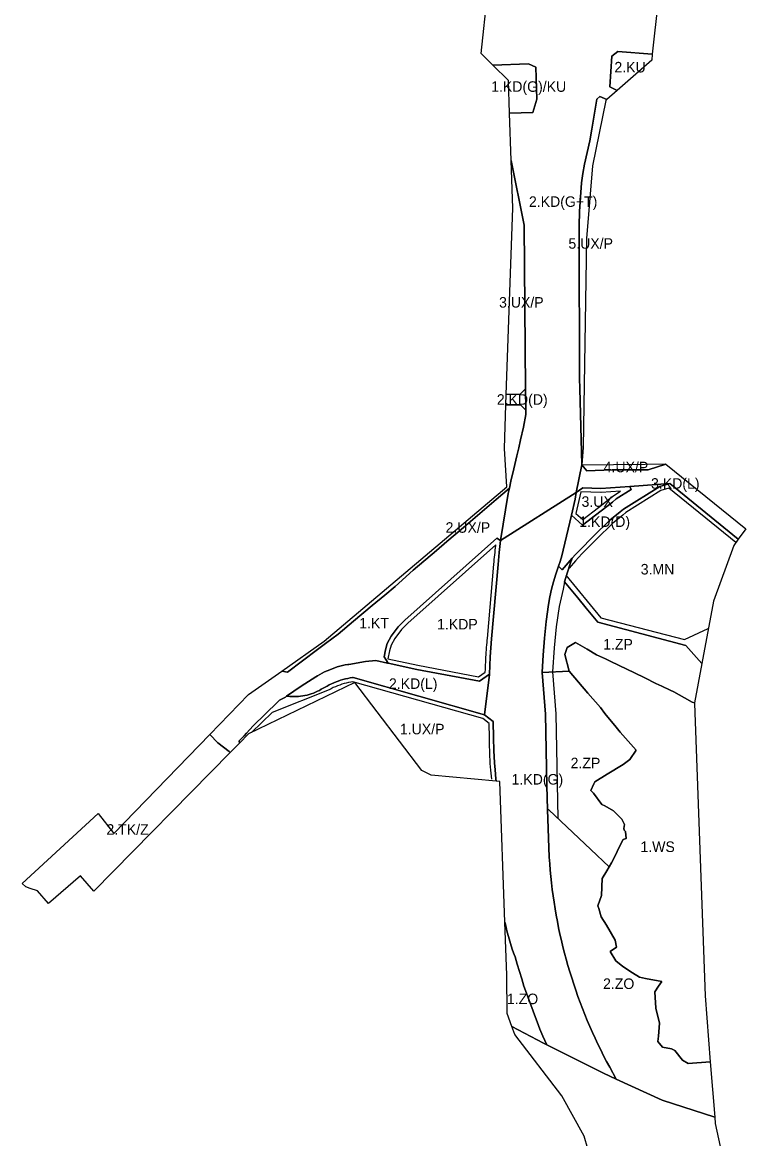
# Model space of a CAD drawing. Extents: x 7426363 to 7427567, y 5543397 to 5546605.
# Drawn here: x 7426639 to 7427327, y 5544381 to 5545441 of the extents above; entities that cross this region are included whole.
import ezdxf

# ---------------------------------------------------------------- set-up
doc = ezdxf.new("R2010")
doc.units = 0
for name, color, linetype in [('linie_rozgraniczajace', 7, 'Continuous'), ('linie_zabudowy_nieprzekraczalne', 7, 'Continuous'), ('oznaczenia_przeznaczen', 7, 'Continuous')]:
    doc.layers.add(name, color=color, linetype=linetype)

msp = doc.modelspace()

# ---------------------------------------------------------------- linework, layer by layer
at = {"layer": 'linie_rozgraniczajace'}
for points in [[(7427243.5, 5545461.5), (7427238, 5545410.3), (7427205.1, 5545413.1), (7427199.7, 5545408.5), (7427197.6, 5545379.3), (7427204.7, 5545376), (7427194.8, 5545367.3), (7427188.1, 5545370.2), (7427185.4, 5545367.6), (7427180.7, 5545339.4), (7427178.5, 5545328.2), (7427173.6, 5545306.2), (7427171.9, 5545297.3), (7427170.8, 5545288.4), (7427169.7, 5545274.8), (7427168.9, 5545261.2), (7427168.5, 5545247.6), (7427168.4, 5545234), (7427168.7, 5545106.2), (7427168.7, 5545102.7), (7427169.2, 5545093.1), (7427171, 5545020.6), (7427165.8, 5544994.3), (7427093.9, 5544949), (7427101.2, 5544993.4), (7427102.2, 5544998.5), (7427103.6, 5545005.2), (7427106.3, 5545016.9), (7427109.3, 5545029.3), (7427111.1, 5545036.8), (7427112.7, 5545044.4), (7427115.5, 5545056.4), (7427117.7, 5545068.5), (7427117.7, 5545072.7), (7427117.5, 5545092.7), (7427116.3, 5545248.3), (7427104, 5545309.5), (7427102.4, 5545354.4), (7427124.6, 5545355.2), (7427128.4, 5545367.6), (7427127.4, 5545398), (7427120.5, 5545401.3), (7427086.5, 5545400.1), (7427075.4, 5545411.1), (7427081.5, 5545467.8)], [(7427187.3, 5544335.4), (7427173.3, 5544383.6), (7427151.9, 5544421.9), (7427107.4, 5544479.9), (7427104.7, 5544487.5), (7427134.6, 5544471.8), (7427137.7, 5544470.2), (7427191.5, 5544443.3), (7427203.7, 5544437.7), (7427247.3, 5544417.6), (7427297.3, 5544401.6), (7427297.8, 5544395.4), (7427304, 5544366.5)]]:
    msp.add_lwpolyline(points, dxfattribs=at)
for points in [[(7427197.6, 5545379.3), (7427199.7, 5545408.5), (7427205.1, 5545413.1), (7427238, 5545410.3), (7427237.4, 5545404.8), (7427204.7, 5545376)], [(7427086.5, 5545400.1), (7427120.5, 5545401.3), (7427127.4, 5545398), (7427128.4, 5545367.6), (7427124.6, 5545355.2), (7427102.4, 5545354.4), (7427101.3, 5545385.4)], [(7427171, 5545020.6), (7427169.2, 5545093.1), (7427168.7, 5545102.7), (7427168.7, 5545106.2), (7427168.4, 5545234), (7427168.5, 5545247.6), (7427168.9, 5545261.2), (7427169.7, 5545274.8), (7427170.8, 5545288.4), (7427171.9, 5545297.3), (7427173.6, 5545306.2), (7427178.5, 5545328.2), (7427180.7, 5545339.4), (7427185.4, 5545367.6), (7427188.1, 5545370.2), (7427194.8, 5545367.3), (7427193.9, 5545366.5), (7427181.1, 5545304.6), (7427175.6, 5545235.4), (7427172.2, 5545037)], [(7427099.3, 5545087.5), (7427105.6, 5545264.4), (7427104, 5545309.5), (7427116.3, 5545248.3), (7427117.5, 5545092.7), (7427112.6, 5545087.7)], [(7427099, 5545077.5), (7427099.3, 5545087.5), (7427112.6, 5545087.7), (7427117.5, 5545092.7), (7427117.7, 5545072.7), (7427112.7, 5545077.7)], [(7426885.9, 5544824.8), (7426926.3, 5544853.3), (7427099.7, 5544999.9), (7427097.5, 5545036.2), (7427099, 5545077.5), (7427112.7, 5545077.7), (7427117.7, 5545072.7), (7427117.7, 5545068.5), (7427115.5, 5545056.4), (7427112.7, 5545044.4), (7427111.1, 5545036.8), (7427109.3, 5545029.3), (7427106.3, 5545016.9), (7427103.6, 5545005.2), (7427102.2, 5544998.5), (7427089.6, 5544987.7), (7427074, 5544974.4), (7427058.5, 5544961.1), (7427042.9, 5544947.9), (7427033, 5544939.5), (7427010.7, 5544920.7), (7426993.7, 5544905.1), (7426983.9, 5544897), (7426971.8, 5544887.1), (7426954.1, 5544872.4), (7426939.4, 5544860), (7426927.6, 5544851.1), (7426919.9, 5544845.4), (7426891.3, 5544823.9)], [(7427165.8, 5544994.3), (7427171, 5545020.6), (7427175.9, 5545015.1), (7427200, 5545015.8), (7427234.1, 5545015.8), (7427251, 5545021.2), (7427326.7, 5544960), (7427319.7, 5544950.2), (7427254.5, 5545002.9), (7427216.5, 5545000.2), (7427189.2, 5544998.3), (7427172, 5544999)], [(7427171, 5545020.6), (7427231.3, 5545021.3), (7427250.4, 5545021.7), (7427251, 5545021.2), (7427234.1, 5545015.8), (7427200, 5545015.8), (7427175.9, 5545015.1)], [(7427148.9, 5544924.6), (7427150.4, 5544929), (7427152, 5544934.2), (7427153.4, 5544939.6), (7427161.1, 5544973), (7427171.7, 5544963.5), (7427189.5, 5544977), (7427200.1, 5544985.4), (7427203.7, 5544988.3), (7427217.8, 5544997.2), (7427216.5, 5545000.2), (7427254.5, 5545002.9), (7427245, 5545000.2), (7427210.7, 5544978.5), (7427207.5, 5544976), (7427197.5, 5544968), (7427182.4, 5544953.3), (7427168.5, 5544939.2), (7427164.9, 5544935.5), (7427161.9, 5544932.2), (7427161.8, 5544932.1), (7427152.3, 5544921.1)], [(7427154.5, 5544909.7), (7427155.7, 5544913.6), (7427159.8, 5544925.8), (7427161.8, 5544932.1), (7427161.9, 5544932.2), (7427164.9, 5544935.5), (7427168.5, 5544939.2), (7427182.4, 5544953.3), (7427197.5, 5544968), (7427207.5, 5544976), (7427210.7, 5544978.5), (7427245, 5545000.2), (7427254.5, 5545002.9), (7427319.7, 5544950.2), (7427315.3, 5544944.1), (7427296.1, 5544891.4), (7427285, 5544832.2), (7427269.9, 5544849.3), (7427186.3, 5544871.2), (7427175.1, 5544884.7), (7427167.4, 5544894.4), (7427157.9, 5544905.7)], [(7426817.6, 5544764.8), (7426854.3, 5544802.7), (7426885.9, 5544824.8), (7426891.3, 5544823.9), (7426919.9, 5544845.4), (7426927.6, 5544851.1), (7426939.4, 5544860), (7426954.1, 5544872.4), (7426971.8, 5544887.1), (7426983.9, 5544897), (7426993.7, 5544905.1), (7427010.7, 5544920.7), (7427033, 5544939.5), (7427042.9, 5544947.9), (7427058.5, 5544961.1), (7427074, 5544974.4), (7427089.6, 5544987.7), (7427102.2, 5544998.5), (7427101.2, 5544993.4), (7427093.9, 5544949), (7427090.4, 5544951.2), (7427003, 5544873.4), (7426996.7, 5544867), (7426990, 5544858), (7426986.1, 5544851), (7426984.4, 5544845.2), (7426983.2, 5544838.4), (7426987.1, 5544832.4), (7426986.5, 5544832.5), (7426975.3, 5544834.9), (7426965.6, 5544834), (7426949.7, 5544831.3), (7426948.8, 5544831.2), (7426946.2, 5544830.7), (7426943.7, 5544830.1), (7426941.2, 5544829.5), (7426938.7, 5544828.8), (7426936.3, 5544828), (7426933.9, 5544827.2), (7426931.5, 5544826.2), (7426929.1, 5544825.2), (7426926.7, 5544824.1), (7426924.4, 5544823), (7426922.2, 5544821.7), (7426920, 5544820.5), (7426918.3, 5544819.6), (7426904.5, 5544810.5), (7426890.6, 5544801.1), (7426889.5, 5544800.3), (7426883.9, 5544797.3), (7426881.9, 5544795.3), (7426858.9, 5544773.1), (7426852.4, 5544765.9), (7426850.2, 5544763.5), (7426845.4, 5544758.7), (7426845.8, 5544756.5), (7426836.9, 5544747.6), (7426836, 5544748.6), (7426825.1, 5544756.9)], [(7427078.7, 5544783.4), (7427083.2, 5544821.6), (7427083.2, 5544821.9), (7427084, 5544838.6), (7427085.3, 5544855.5), (7427091.5, 5544926), (7427092.6, 5544937.5), (7427093.9, 5544949), (7427165.8, 5544994.3), (7427164.6, 5544988.2), (7427161.1, 5544973), (7427153.4, 5544939.6), (7427152, 5544934.2), (7427150.4, 5544929), (7427148.9, 5544924.6), (7427146.2, 5544916.8), (7427144.1, 5544909.7), (7427142.2, 5544902.6), (7427140.7, 5544895.3), (7427139.5, 5544888.1), (7427137.3, 5544872.1), (7427135.5, 5544856.1), (7427134.2, 5544840), (7427133.3, 5544824), (7427133.3, 5544823.6), (7427136.5, 5544783.9), (7427137.7, 5544716.1), (7427138.5, 5544693.6), (7427140.1, 5544648.3), (7427140.5, 5544642.1), (7427141, 5544636), (7427141.6, 5544629.9), (7427142.2, 5544623.8), (7427143, 5544617.7), (7427143.8, 5544611.5), (7427144.7, 5544605.5), (7427145.6, 5544599.4), (7427146.7, 5544593.3), (7427147.8, 5544587.3), (7427149, 5544581.3), (7427150.3, 5544575.2), (7427151.7, 5544569.3), (7427153.1, 5544563.3), (7427154.6, 5544557.3), (7427156.2, 5544551.4), (7427157.8, 5544545.5), (7427159.6, 5544539.6), (7427161.4, 5544533.7), (7427163.3, 5544527.8), (7427165.2, 5544522), (7427167.3, 5544516.2), (7427169.4, 5544510.4), (7427171.6, 5544504.7), (7427173.9, 5544499), (7427176.2, 5544493.3), (7427178.6, 5544487.6), (7427181.1, 5544482), (7427183.6, 5544476.4), (7427186.3, 5544470.9), (7427189, 5544465.3), (7427191.7, 5544459.8), (7427194.6, 5544454.4), (7427197.5, 5544449), (7427203.7, 5544437.7), (7427191.5, 5544443.3), (7427137.7, 5544470.2), (7427134.1, 5544478.5), (7427131.3, 5544485.2), (7427128.6, 5544492), (7427126, 5544498.7), (7427123.4, 5544505.5), (7427120.9, 5544512.3), (7427118.5, 5544519.2), (7427116.1, 5544526), (7427113.9, 5544532.9), (7427111.7, 5544539.8), (7427109.5, 5544546.8), (7427107.6, 5544553.6), (7427106.7, 5544555.8), (7427105.3, 5544560), (7427103.9, 5544564.3), (7427102.6, 5544568.6), (7427101.4, 5544572.9), (7427100.2, 5544577.2), (7427099.1, 5544581.5), (7427098.2, 5544585.9), (7427098, 5544586.7), (7427093.2, 5544720), (7427089.7, 5544720.3), (7427089.5, 5544722.5), (7427088.7, 5544731.3), (7427088.1, 5544737.7), (7427087.5, 5544749.6), (7427087.2, 5544761.6), (7427086.9, 5544777)], [(7427161.1, 5544973), (7427164.6, 5544988.2), (7427165.8, 5544994.3), (7427172, 5544999), (7427189.2, 5544998.3), (7427216.5, 5545000.2), (7427217.8, 5544997.2), (7427203.7, 5544988.3), (7427200.1, 5544985.4), (7427189.5, 5544977), (7427171.7, 5544963.5)], [(7426983.2, 5544838.4), (7426984.4, 5544845.2), (7426986.1, 5544851), (7426990, 5544858), (7426996.7, 5544867), (7427003, 5544873.4), (7427090.4, 5544951.2), (7427093.9, 5544949), (7427092.6, 5544937.5), (7427091.5, 5544926), (7427085.3, 5544855.5), (7427084, 5544838.6), (7427083.2, 5544821.9), (7427073.9, 5544815.4), (7427014.4, 5544826.5), (7426987.1, 5544832.4)], [(7427133.3, 5544824), (7427134.2, 5544840), (7427135.5, 5544856.1), (7427137.3, 5544872.1), (7427139.5, 5544888.1), (7427140.7, 5544895.3), (7427142.2, 5544902.6), (7427144.1, 5544909.7), (7427146.2, 5544916.8), (7427148.9, 5544924.6), (7427152.3, 5544921.1), (7427161.8, 5544932.1), (7427159.8, 5544925.8), (7427155.7, 5544913.6), (7427154.5, 5544909.7), (7427157.9, 5544905.7), (7427167.4, 5544894.4), (7427175.1, 5544884.7), (7427186.3, 5544871.2), (7427269.9, 5544849.3), (7427285, 5544832.2), (7427278.1, 5544794.7), (7427275.8, 5544795.5), (7427268.5, 5544799.6), (7427258.6, 5544805.3), (7427255, 5544806.9), (7427247.1, 5544810.7), (7427241.5, 5544813.2), (7427230.8, 5544818.4), (7427221, 5544823.3), (7427206.6, 5544830.2), (7427197.9, 5544834.3), (7427193.4, 5544836.4), (7427185, 5544840.4), (7427176, 5544845.8), (7427164.9, 5544852.2), (7427157.2, 5544847.4), (7427155, 5544840.8), (7427159.1, 5544824.7), (7427133.3, 5544823.6)], [(7427155, 5544840.8), (7427157.2, 5544847.4), (7427164.9, 5544852.2), (7427176, 5544845.8), (7427185, 5544840.4), (7427193.4, 5544836.4), (7427197.9, 5544834.3), (7427206.6, 5544830.2), (7427221, 5544823.3), (7427230.8, 5544818.4), (7427241.5, 5544813.2), (7427247.1, 5544810.7), (7427255, 5544806.9), (7427258.6, 5544805.3), (7427268.5, 5544799.6), (7427275.8, 5544795.5), (7427278.1, 5544794.7), (7427278, 5544794.3), (7427288.1, 5544516.8), (7427293, 5544454.2), (7427272, 5544452.5), (7427266.7, 5544455.5), (7427259.4, 5544464.8), (7427256.3, 5544466.5), (7427247.7, 5544468.1), (7427243.2, 5544473.4), (7427243.8, 5544478.4), (7427244.8, 5544490.6), (7427241.4, 5544505), (7427240.3, 5544520.6), (7427243.8, 5544526), (7427246.9, 5544530.3), (7427231.5, 5544533.3), (7427225.7, 5544534.3), (7427219.1, 5544538.6), (7427209.9, 5544544.4), (7427203.5, 5544549.9), (7427198, 5544558.7), (7427204, 5544562.9), (7427202.8, 5544569.4), (7427194.4, 5544583.8), (7427189.5, 5544591.6), (7427187.3, 5544599.6), (7427186.4, 5544602.1), (7427189.6, 5544611.9), (7427190.3, 5544628), (7427194.7, 5544635.3), (7427197, 5544639.2), (7427199.2, 5544642.8), (7427201.7, 5544647.7), (7427207.6, 5544659.7), (7427210.4, 5544665.1), (7427213.1, 5544665.9), (7427212.4, 5544672.6), (7427211.2, 5544673.9), (7427211.1, 5544675.4), (7427211.5, 5544679.2), (7427208.9, 5544684.3), (7427201.2, 5544692.3), (7427193, 5544696.9), (7427190.2, 5544698.4), (7427182, 5544708.9), (7427179.7, 5544711.6), (7427182.4, 5544718), (7427183.5, 5544719.9), (7427195, 5544727), (7427210.2, 5544736.4), (7427216.5, 5544741), (7427222.7, 5544749.8), (7427207.4, 5544766.8), (7427203.6, 5544771.7), (7427193, 5544784.8), (7427188.9, 5544790.2), (7427176.9, 5544804.1), (7427159.1, 5544824.7)], [(7426890.6, 5544801.1), (7426904.5, 5544810.5), (7426918.3, 5544819.6), (7426920, 5544820.5), (7426922.2, 5544821.7), (7426924.4, 5544823), (7426926.7, 5544824.1), (7426929.1, 5544825.2), (7426931.5, 5544826.2), (7426933.9, 5544827.2), (7426936.3, 5544828), (7426938.7, 5544828.8), (7426941.2, 5544829.5), (7426943.7, 5544830.1), (7426946.2, 5544830.7), (7426948.8, 5544831.2), (7426949.7, 5544831.3), (7426965.6, 5544834), (7426975.3, 5544834.9), (7426986.5, 5544832.5), (7426987.1, 5544832.4), (7427014.4, 5544826.5), (7427073.9, 5544815.4), (7427083.2, 5544821.9), (7427083.2, 5544821.6), (7427078.7, 5544783.4), (7426953.7, 5544818.9), (7426953.3, 5544818.8), (7426951, 5544818.5), (7426948.7, 5544818), (7426946.4, 5544817.5), (7426944.1, 5544816.9), (7426941.9, 5544816.2), (7426939.7, 5544815.5), (7426937.5, 5544814.7), (7426935.3, 5544813.8), (7426933.2, 5544812.8), (7426931.1, 5544811.8), (7426929, 5544810.7), (7426923.5, 5544807.6), (7426921.7, 5544806.6), (7426919.8, 5544805.7), (7426917.9, 5544804.9), (7426916, 5544804.1), (7426914, 5544803.4), (7426912, 5544802.8), (7426910, 5544802.2), (7426908, 5544801.8), (7426906, 5544801.4), (7426903.9, 5544801.1), (7426901.8, 5544800.9), (7426899.8, 5544800.7), (7426897.7, 5544800.7), (7426895.6, 5544800.7), (7426893.5, 5544800.8), (7426891.5, 5544801)], [(7427138.5, 5544693.6), (7427137.7, 5544716.1), (7427136.5, 5544783.9), (7427133.3, 5544823.6), (7427159.1, 5544824.7), (7427176.9, 5544804.1), (7427188.9, 5544790.2), (7427193, 5544784.8), (7427203.6, 5544771.7), (7427207.4, 5544766.8), (7427222.7, 5544749.8), (7427216.5, 5544741), (7427210.2, 5544736.4), (7427195, 5544727), (7427183.5, 5544719.9), (7427182.4, 5544718), (7427179.7, 5544711.6), (7427182, 5544708.9), (7427190.2, 5544698.4), (7427193, 5544696.9), (7427201.2, 5544692.3), (7427208.9, 5544684.3), (7427211.5, 5544679.2), (7427211.1, 5544675.4), (7427211.2, 5544673.9), (7427212.4, 5544672.6), (7427213.1, 5544665.9), (7427210.4, 5544665.1), (7427207.6, 5544659.7), (7427201.7, 5544647.7), (7427199.2, 5544642.8), (7427197, 5544639.2), (7427179.5, 5544655.7), (7427139.6, 5544693.2)], [(7426845.4, 5544758.7), (7426850.2, 5544763.5), (7426852.4, 5544765.9), (7426858.9, 5544773.1), (7426881.9, 5544795.3), (7426883.9, 5544797.3), (7426889.5, 5544800.3), (7426890.6, 5544801.1), (7426891.5, 5544801), (7426893.5, 5544800.8), (7426895.6, 5544800.7), (7426897.7, 5544800.7), (7426899.8, 5544800.7), (7426901.8, 5544800.9), (7426903.9, 5544801.1), (7426906, 5544801.4), (7426908, 5544801.8), (7426910, 5544802.2), (7426912, 5544802.8), (7426914, 5544803.4), (7426916, 5544804.1), (7426917.9, 5544804.9), (7426919.8, 5544805.7), (7426921.7, 5544806.6), (7426923.5, 5544807.6), (7426929, 5544810.7), (7426931.1, 5544811.8), (7426933.2, 5544812.8), (7426935.3, 5544813.8), (7426937.5, 5544814.7), (7426939.7, 5544815.5), (7426941.9, 5544816.2), (7426944.1, 5544816.9), (7426946.4, 5544817.5), (7426948.7, 5544818), (7426951, 5544818.5), (7426953.3, 5544818.8), (7426953.7, 5544818.9), (7427078.7, 5544783.4), (7427086.9, 5544777), (7427087.2, 5544761.6), (7427087.5, 5544749.6), (7427088.1, 5544737.7), (7427088.7, 5544731.3), (7427089.5, 5544722.5), (7427089.7, 5544720.3), (7427028, 5544726.2), (7427019.2, 5544730.7), (7426955.5, 5544814.2), (7426854.4, 5544765.4), (7426845.8, 5544756.5)], [(7426639.5, 5544623.2), (7426711.6, 5544689.6), (7426726.5, 5544670.7), (7426817.6, 5544764.8), (7426825.1, 5544756.9), (7426836, 5544748.6), (7426836.9, 5544747.6), (7426707.3, 5544615.9), (7426694.8, 5544630.6), (7426664.4, 5544604.3), (7426653.8, 5544616.5), (7426646.9, 5544618.7), (7426642.7, 5544620.1)], [(7427140.1, 5544648.3), (7427138.5, 5544693.6), (7427139.6, 5544693.2), (7427179.5, 5544655.7), (7427197, 5544639.2), (7427194.7, 5544635.3), (7427190.3, 5544628), (7427189.6, 5544611.9), (7427186.4, 5544602.1), (7427187.3, 5544599.6), (7427189.5, 5544591.6), (7427194.4, 5544583.8), (7427202.8, 5544569.4), (7427204, 5544562.9), (7427198, 5544558.7), (7427203.5, 5544549.9), (7427209.9, 5544544.4), (7427219.1, 5544538.6), (7427225.7, 5544534.3), (7427231.5, 5544533.3), (7427246.9, 5544530.3), (7427243.8, 5544526), (7427240.3, 5544520.6), (7427241.4, 5544505), (7427244.8, 5544490.6), (7427243.8, 5544478.4), (7427243.2, 5544473.4), (7427247.7, 5544468.1), (7427256.3, 5544466.5), (7427259.4, 5544464.8), (7427266.7, 5544455.5), (7427272, 5544452.5), (7427293, 5544454.2), (7427297.3, 5544401.6), (7427247.3, 5544417.6), (7427203.7, 5544437.7), (7427197.5, 5544449), (7427194.6, 5544454.4), (7427191.7, 5544459.8), (7427189, 5544465.3), (7427186.3, 5544470.9), (7427183.6, 5544476.4), (7427181.1, 5544482), (7427178.6, 5544487.6), (7427176.2, 5544493.3), (7427173.9, 5544499), (7427171.6, 5544504.7), (7427169.4, 5544510.4), (7427167.3, 5544516.2), (7427165.2, 5544522), (7427163.3, 5544527.8), (7427161.4, 5544533.7), (7427159.6, 5544539.6), (7427157.8, 5544545.5), (7427156.2, 5544551.4), (7427154.6, 5544557.3), (7427153.1, 5544563.3), (7427151.7, 5544569.3), (7427150.3, 5544575.2), (7427149, 5544581.3), (7427147.8, 5544587.3), (7427146.7, 5544593.3), (7427145.6, 5544599.4), (7427144.7, 5544605.5), (7427143.8, 5544611.5), (7427143, 5544617.7), (7427142.2, 5544623.8), (7427141.6, 5544629.9), (7427141, 5544636), (7427140.5, 5544642.1)], [(7427100.2, 5544499.8), (7427099.8, 5544536.3), (7427098, 5544586.7), (7427098.2, 5544585.9), (7427099.1, 5544581.5), (7427100.2, 5544577.2), (7427101.4, 5544572.9), (7427102.6, 5544568.6), (7427103.9, 5544564.3), (7427105.3, 5544560), (7427106.7, 5544555.8), (7427107.6, 5544553.6), (7427109.5, 5544546.8), (7427111.7, 5544539.8), (7427113.9, 5544532.9), (7427116.1, 5544526), (7427118.5, 5544519.2), (7427120.9, 5544512.3), (7427123.4, 5544505.5), (7427126, 5544498.7), (7427128.6, 5544492), (7427131.3, 5544485.2), (7427134.1, 5544478.5), (7427137.7, 5544470.2), (7427134.6, 5544471.8), (7427104.7, 5544487.5)]]:
    msp.add_lwpolyline(points, close=True, dxfattribs=at)
at = {"layer": 'linie_zabudowy_nieprzekraczalne'}
for points in [[(7427317.2, 5544947.1), (7427253.6, 5544998.5), (7427246.1, 5544996.3), (7427213, 5544975.3), (7427210, 5544972.9), (7427200.1, 5544965), (7427185.2, 5544950.5), (7427171.4, 5544936.4), (7427167.9, 5544932.7), (7427164.9, 5544929.5), (7427159, 5544922.6)], [(7427165.5, 5544974.4), (7427171.9, 5544968.7), (7427187, 5544980.2), (7427197.6, 5544988.6), (7427201.4, 5544991.6), (7427207.7, 5544995.6), (7427189.5, 5544994.3), (7427189.1, 5544994.3), (7427170.2, 5544995), (7427165.5, 5544974.4)], [(7426986.9, 5544836.5), (7427015.2, 5544830.4), (7427073, 5544819.6), (7427079.3, 5544824), (7427079.4, 5544826.4), (7427079.5, 5544828.7), (7427079.6, 5544831), (7427079.7, 5544833.4), (7427079.8, 5544835.7), (7427080, 5544838), (7427080.1, 5544840.4), (7427080.3, 5544842.7), (7427080.4, 5544845), (7427080.6, 5544847.3), (7427080.8, 5544849.7), (7427081, 5544852), (7427081.1, 5544854.3), (7427081.3, 5544855.9), (7427087.5, 5544926.3), (7427087.7, 5544928.5), (7427087.9, 5544930.8), (7427088.1, 5544933), (7427088.3, 5544935.2), (7427088.6, 5544937.5), (7427088.8, 5544939.7), (7427089.1, 5544941.9), (7427089.3, 5544944.2), (7427089.4, 5544944.9), (7427005.8, 5544870.5), (7426999.7, 5544864.4), (7426993.4, 5544855.9), (7426989.8, 5544849.4), (7426988.3, 5544844.2), (7426986.9, 5544836.5)], [(7427154.5, 5544909.7), (7427153.3, 5544902.7), (7427149.4, 5544886.1), (7427146.8, 5544866.8), (7427144.8, 5544846.9), (7427143.3, 5544824.3), (7427146.5, 5544784.3), (7427148.2, 5544685)], [(7427156, 5544915.8), (7427189.1, 5544875.6)], [(7427189.1, 5544875.6), (7427268.7, 5544854.8), (7427291.1, 5544865.4)], [(7427085.5, 5544722.2), (7427084.7, 5544731), (7427084.1, 5544737.3), (7427084.1, 5544737.4), (7427084, 5544739.3), (7427083.9, 5544741.2), (7427083.8, 5544743.1), (7427083.7, 5544745), (7427083.6, 5544746.8), (7427083.5, 5544748.7), (7427083.5, 5544750.6), (7427083.4, 5544752.5), (7427083.3, 5544754.4), (7427083.3, 5544756.3), (7427083.2, 5544758.2), (7427083.2, 5544760.1), (7427083.2, 5544761.5), (7427083.2, 5544761.5), (7427082.9, 5544775.1), (7427076.9, 5544779.8), (7426953.4, 5544814.8), (7426951.7, 5544814.5), (7426949.5, 5544814.1), (7426947.3, 5544813.6), (7426945.2, 5544813.1), (7426943.1, 5544812.4), (7426941, 5544811.7), (7426938.9, 5544811), (7426936.9, 5544810.1), (7426934.9, 5544809.2), (7426932.9, 5544808.2), (7426930.9, 5544807.2), (7426877, 5544785.6), (7426857.3, 5544766.7)]]:
    msp.add_lwpolyline(points, dxfattribs=at)

# ---------------------------------------------------------------- texts
at = {"layer": 'oznaczenia_przeznaczen'}
for s, p in [('2.KU', (7427202, 5545393.1)), ('1.KD(G)/KU', (7427084.9, 5545374.7)), ('2.KD(G+T)', (7427120.8, 5545265.5)), ('5.UX/P', (7427158.3, 5545225.8)), ('3.UX/P', (7427092.4, 5545169.9)), ('2.KD(D)', (7427090.3, 5545077.7)), ('4.UX/P', (7427191.8, 5545013.6)), ('3.KD(L)', (7427236.8, 5544998)), ('3.UX', (7427170.8, 5544980.8)), ('1.KD(D)', (7427168.6, 5544961.7)), ('2.UX/P', (7427041.6, 5544956.2)), ('3.MN', (7427227, 5544916.6)), ('1.KT', (7426959.6, 5544865.4)), ('1.KDP', (7427033.5, 5544864.4)), ('1.ZP', (7427191.3, 5544845.4)), ('2.KD(L)', (7426987.8, 5544808)), ('1.UX/P', (7426998.2, 5544764.9)), ('2.ZP', (7427160.4, 5544732.7)), ('1.KD(G)', (7427104.3, 5544717.2)), ('2.TK/Z', (7426719.4, 5544669.6)), ('1.WS', (7427226.7, 5544653.2)), ('2.ZO', (7427191.2, 5544523.2)), ('1.ZO', (7427099.9, 5544508.8))]:
    msp.add_text(s, height=10, dxfattribs=at).set_placement(p)

doc.saveas('drawing.dxf')
